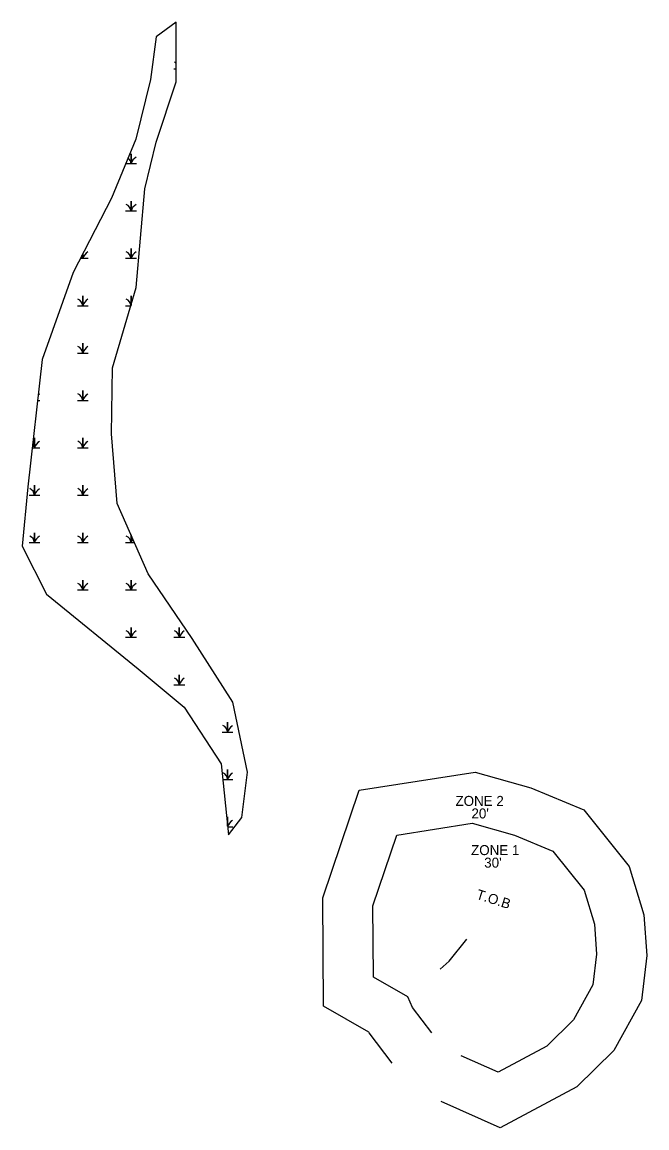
# Model space of a CAD drawing. Extents: x 2091245 to 2092168, y 863656 to 864307.
# Drawn here: x 2091244.7 to 2091494.5, y 863656.1 to 864098.3 of the extents above; entities that cross this region are included whole.
import ezdxf

# ---------------------------------------------------------------- set-up
doc = ezdxf.new("R2010")
doc.units = 0
for name, color, linetype in [('Exist Environmental Wetland Boundary', 7, 'Continuous'), ('Exist Hydro Jurisdictional Stream or Body of Water', 7, 'Continuous'), ('Exist Hydro Swamp or Marsh', 7, 'Continuous'), ('Prop Boundary Buffer Zone 1', 7, 'Continuous'), ('Prop Boundary Buffer Zone 2', 7, 'Continuous'), ('Scratch_Level_6', 7, 'Continuous')]:
    doc.layers.add(name, color=color, linetype=linetype)

msp = doc.modelspace()

# ---------------------------------------------------------------- linework, layer by layer
at = {"layer": 'Exist Environmental Wetland Boundary'}
msp.add_lwpolyline([(2091306.38, 864098.3), (2091298.37, 864092.45), (2091296.03, 864075.33), (2091290.2, 864051.48), (2091280.49, 864027.85), (2091265.1, 863998.19), (2091252.76, 863963.33), (2091247.03, 863912.5), (2091244.74, 863888.7), (2091254.43, 863869.52), (2091291.1, 863839.63), (2091309.5, 863824.39), (2091324.26, 863801.64), (2091327.23, 863773.24), (2091332.59, 863780.27), (2091334.83, 863798.29), (2091329, 863826.29), (2091312.68, 863851.84), (2091295.19, 863877.67), (2091282.73, 863905.82), (2091280.44, 863933.67), (2091280.92, 863960.09), (2091290.39, 863992.18), (2091293.81, 864031.61), (2091298.38, 864050.26), (2091306.3, 864074.45)], close=True, dxfattribs=at)
at = {"layer": 'Exist Hydro Jurisdictional Stream or Body of Water'}
msp.add_lwpolyline([(2091411.81, 863719.6), (2091415.44, 863722.79), (2091422.46, 863731.55)], dxfattribs=at)
at = {"layer": 'Exist Hydro Swamp or Marsh'}
for p, q in [((2091305.42, 864079.62), (2091306.32, 864079.62)), ((2091286.12, 863984.9), (2091288.24, 863984.9)), ((2091250.92, 863947.01), (2091251.82, 863947.01)), ((2091326.89, 863776.5), (2091329.02, 863776.5))]:
    msp.add_line(p, q, dxfattribs=at)
for points in [[(2091286.2, 864041.73), (2091288.27, 864041.73), (2091288.27, 864045.68), (2091288.27, 864041.73), (2091290.42, 864041.73)], [(2091286.12, 864022.79), (2091288.27, 864022.79), (2091288.27, 864026.73), (2091288.27, 864022.79), (2091290.42, 864022.79)], [(2091268.04, 864003.84), (2091268.97, 864003.84), (2091268.97, 864005.63)], [(2091268.97, 864005.63), (2091268.97, 864003.84), (2091271.12, 864003.84)], [(2091286.12, 864003.84), (2091288.27, 864003.84), (2091288.27, 864007.79), (2091288.27, 864003.84), (2091290.42, 864003.84)], [(2091266.82, 863984.9), (2091268.97, 863984.9), (2091268.97, 863988.84), (2091268.97, 863984.9), (2091271.12, 863984.9)], [(2091288.27, 863984.98), (2091288.27, 863988.84), (2091288.27, 863984.98)], [(2091266.82, 863965.95), (2091268.97, 863965.95), (2091268.97, 863969.9), (2091268.97, 863965.95), (2091271.12, 863965.95)], [(2091266.82, 863947.01), (2091268.97, 863947.01), (2091268.97, 863950.95), (2091268.97, 863947.01), (2091271.12, 863947.01)], [(2091248.78, 863928.06), (2091249.66, 863928.06), (2091249.66, 863932.01), (2091249.66, 863928.06), (2091251.82, 863928.06)], [(2091266.82, 863928.06), (2091268.97, 863928.06), (2091268.97, 863932.01), (2091268.97, 863928.06), (2091271.12, 863928.06)], [(2091247.51, 863909.12), (2091249.66, 863909.12), (2091249.66, 863913.06), (2091249.66, 863909.12), (2091251.82, 863909.12)], [(2091266.82, 863909.12), (2091268.97, 863909.12), (2091268.97, 863913.06), (2091268.97, 863909.12), (2091271.12, 863909.12)], [(2091247.51, 863890.17), (2091249.66, 863890.17), (2091249.66, 863894.12), (2091249.66, 863890.17), (2091251.82, 863890.17)], [(2091266.82, 863890.17), (2091268.97, 863890.17), (2091268.97, 863894.12), (2091268.97, 863890.17), (2091271.12, 863890.17)], [(2091286.12, 863890.17), (2091288.27, 863890.17), (2091288.27, 863893.31)], [(2091288.27, 863893.31), (2091288.27, 863890.17), (2091289.66, 863890.17)], [(2091266.82, 863871.23), (2091268.97, 863871.23), (2091268.97, 863875.17), (2091268.97, 863871.23), (2091271.12, 863871.23)], [(2091286.12, 863871.23), (2091288.27, 863871.23), (2091288.27, 863875.17), (2091288.27, 863871.23), (2091290.42, 863871.23)], [(2091286.12, 863852.28), (2091288.27, 863852.28), (2091288.27, 863856.23), (2091288.27, 863852.28), (2091290.42, 863852.28)], [(2091305.42, 863852.28), (2091307.57, 863852.28), (2091307.57, 863856.23), (2091307.57, 863852.28), (2091309.72, 863852.28)], [(2091305.42, 863833.33), (2091307.57, 863833.33), (2091307.57, 863837.28), (2091307.57, 863833.33), (2091309.72, 863833.33)], [(2091324.72, 863814.39), (2091326.87, 863814.39), (2091326.87, 863818.33), (2091326.87, 863814.39), (2091329.02, 863814.39)], [(2091324.9, 863795.44), (2091326.87, 863795.44), (2091326.87, 863799.39), (2091326.87, 863795.44), (2091329.02, 863795.44)], [(2091326.87, 863776.69), (2091326.87, 863780.44), (2091326.87, 863776.69)]]:
    msp.add_lwpolyline(points, dxfattribs=at)
for centre, radius, start, end in [((2091304.5, 864079.4), 3.07, 53.6151, 67.535), ((2091285.2, 864041.51), 3.07, 4.1403, 51.8699), ((2091292.83, 864040.22), 4.81, 122.1274, 161.6222), ((2091285.2, 864022.56), 3.07, 4.1403, 67.535), ((2091292.83, 864021.27), 4.81, 122.1274, 161.6222), ((2091265.9, 864003.62), 3.07, 4.1403, 26.8464), ((2091273.53, 864002.33), 4.81, 122.1274, 161.6222), ((2091285.2, 864003.62), 3.07, 4.1403, 67.535), ((2091292.83, 864002.33), 4.81, 122.1274, 161.6222), ((2091265.9, 863984.67), 3.07, 4.1403, 67.535), ((2091273.53, 863983.38), 4.81, 122.1274, 161.6222), ((2091285.2, 863984.67), 3.07, 5.3334, 67.535), ((2091265.9, 863965.73), 3.07, 4.1403, 67.535), ((2091273.53, 863964.44), 4.81, 122.1274, 161.6222), ((2091254.23, 863945.49), 4.81, 122.1274, 129.5296), ((2091265.9, 863946.78), 3.07, 4.1403, 67.535), ((2091273.53, 863945.49), 4.81, 122.1274, 161.6222), ((2091246.6, 863927.84), 3.07, 4.1403, 39.2983), ((2091254.23, 863926.55), 4.81, 122.1274, 161.6222), ((2091265.9, 863927.84), 3.07, 4.1403, 67.535), ((2091273.53, 863926.55), 4.81, 122.1274, 161.6222), ((2091246.6, 863908.89), 3.07, 4.1403, 67.535), ((2091254.23, 863907.6), 4.81, 122.1274, 161.6222), ((2091265.9, 863908.89), 3.07, 4.1403, 67.535), ((2091273.53, 863907.6), 4.81, 122.1274, 161.6222), ((2091246.6, 863889.95), 3.07, 4.1403, 67.535), ((2091254.23, 863888.66), 4.81, 122.1274, 161.6222), ((2091265.9, 863889.95), 3.07, 4.1403, 67.535), ((2091273.53, 863888.66), 4.81, 122.1274, 161.6222), ((2091285.2, 863889.95), 3.07, 4.1403, 67.535), ((2091292.83, 863888.66), 4.81, 142.2612, 161.6222), ((2091265.9, 863871), 3.07, 4.1403, 67.535), ((2091273.53, 863869.71), 4.81, 122.1274, 161.6222), ((2091285.2, 863871), 3.07, 4.1403, 67.535), ((2091292.83, 863869.71), 4.81, 122.1274, 161.6222), ((2091285.2, 863852.06), 3.07, 4.1403, 67.535), ((2091292.83, 863850.76), 4.81, 122.1274, 161.6222), ((2091304.5, 863852.06), 3.07, 4.1403, 67.535), ((2091312.13, 863850.76), 4.81, 122.1274, 161.6222), ((2091304.5, 863833.11), 3.07, 4.1403, 67.535), ((2091312.13, 863831.82), 4.81, 122.1274, 161.6222), ((2091323.8, 863814.17), 3.07, 4.1403, 67.535), ((2091331.43, 863812.87), 4.81, 122.1274, 161.6222), ((2091323.8, 863795.22), 3.07, 4.1403, 67.535), ((2091331.43, 863793.93), 4.81, 122.1274, 161.6222), ((2091331.43, 863774.98), 4.81, 122.1274, 161.052)]:
    msp.add_arc(centre, radius, start, end, dxfattribs=at)
at = {"layer": 'Prop Boundary Buffer Zone 1'}
msp.add_lwpolyline([(2091408.59, 863694.12), (2091400.83, 863704.3), (2091398.96, 863708.53), (2091385.16, 863716.4), (2091384.97, 863744.92), (2091394.55, 863773.22), (2091424.62, 863777.93), (2091441.52, 863773.14), (2091456.86, 863766.78), (2091469.41, 863751.13), (2091473.52, 863737.55), (2091474.41, 863725.51), (2091472.93, 863713.25), (2091465.17, 863699.25), (2091454.54, 863688.73), (2091435.08, 863678.33), (2091420.29, 863684.88)], dxfattribs=at)
at = {"layer": 'Prop Boundary Buffer Zone 2'}
msp.add_lwpolyline([(2091392.68, 863681.99), (2091383.49, 863694.05), (2091383.33, 863694.42), (2091365.23, 863704.73), (2091364.95, 863748.15), (2091379.49, 863791.1), (2091425.86, 863798.37), (2091448.1, 863792.06), (2091469.25, 863783.3), (2091487.43, 863760.62), (2091493.3, 863741.23), (2091494.5, 863725.04), (2091492.31, 863706.97), (2091481.27, 863687.06), (2091466.54, 863672.47), (2091435.91, 863656.09), (2091412.2, 863666.59)], dxfattribs=at)

# ---------------------------------------------------------------- texts
at = {"layer": 'Scratch_Level_6'}
for s, p in [('ZONE 2', (2091417.98, 863784.85)), ("20'", (2091424.37, 863779.84)), ('ZONE 1', (2091424.21, 863765.18)), ("30'", (2091429.47, 863760.17))]:
    msp.add_text(s, height=4, dxfattribs=at).set_placement(p)
msp.add_text('T.O.B', height=4, rotation=342.3945, dxfattribs=at).set_placement((2091425.96, 863747.79))

doc.saveas('drawing.dxf')
